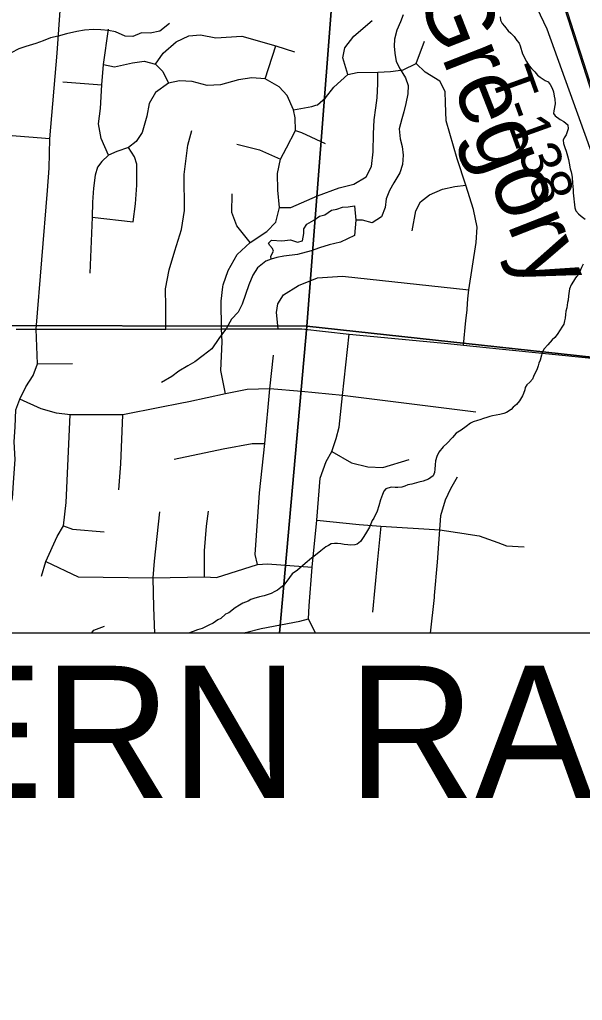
# Model space of a CAD drawing. Extents: x 0 to 34, y 0 to 22.
# Drawn here: x 7.388 to 8.182, y 18.207 to 19.591 of the extents above; entities that cross this region are included whole.
import ezdxf

# ---------------------------------------------------------------- set-up
doc = ezdxf.new("R2010")
doc.units = 0
for name, color, linetype in [('GM_X_County_Road', 7, 'Continuous'), ('GM_X_Minor_River', 7, 'Continuous'), ('GM_X_Minor_River_Text', 7, 'Continuous'), ('GM_X_Rail_Line', 7, 'Continuous'), ('GM_X_Section', 7, 'Continuous'), ('GM_X_Township_Road', 7, 'Continuous'), ('GM_X_Township_Road_Text', 7, 'Continuous'), ('SH_Text', 7, 'Continuous')]:
    doc.layers.add(name, color=color, linetype=linetype)

msp = doc.modelspace()

# ---------------------------------------------------------------- linework, layer by layer
at = {"layer": 'GM_X_County_Road'}
for points in [[(7.3836, 19.1544), (7.4116, 19.1543), (7.5209, 19.1543), (7.5946, 19.1542), (7.6731, 19.1546), (7.7531, 19.1546), (7.7867, 19.1546), (7.8535, 19.1472), (7.9926, 19.134)], [(7.9926, 19.134), (8.0146, 19.1319), (8.0648, 19.1263), (8.261, 19.1068)]]:
    msp.add_lwpolyline(points, dxfattribs=at)
at = {"layer": 'GM_X_Minor_River'}
for points in [[(7.9296, 19.5977), (7.9259, 19.5879), (7.9207, 19.5763), (7.9173, 19.5634), (7.9167, 19.5536), (7.9176, 19.5437), (7.9195, 19.5318), (7.9253, 19.521), (7.933, 19.5087), (7.9365, 19.4983), (7.9362, 19.4862), (7.9332, 19.4726), (7.9303, 19.4608), (7.9278, 19.451), (7.924, 19.4371), (7.9255, 19.4229), (7.9283, 19.4122), (7.9295, 19.3997), (7.9288, 19.3864), (7.9247, 19.3747), (7.9164, 19.3608), (7.9104, 19.35), (7.9056, 19.3383), (7.9041, 19.3258), (7.8988, 19.3126), (7.8857, 19.3042), (7.8721, 19.308)], [(7.5999, 19.5856), (7.586, 19.5749), (7.5726, 19.5718), (7.5605, 19.5722), (7.5482, 19.5671), (7.5372, 19.5678), (7.5237, 19.5739), (7.5138, 19.5756), (7.5032, 19.5767), (7.4926, 19.5773), (7.48, 19.5761), (7.469, 19.5741), (7.4545, 19.5711), (7.4426, 19.5679), (7.4319, 19.5652), (7.4215, 19.5609), (7.4112, 19.5573), (7.3974, 19.5531), (7.3874, 19.5496), (7.3767, 19.5441), (7.3624, 19.5346), (7.3493, 19.5274)], [(8.0662, 19.5951), (8.0668, 19.5901), (8.0693, 19.5858), (8.0723, 19.5819), (8.0778, 19.5753), (8.0815, 19.5718), (8.0859, 19.5671), (8.0899, 19.5616), (8.0932, 19.5577), (8.0946, 19.5543), (8.0977, 19.5428), (8.1035, 19.532), (8.1075, 19.5258), (8.1104, 19.5222), (8.1152, 19.5172), (8.1192, 19.5125), (8.123, 19.5097), (8.13, 19.5053), (8.1342, 19.5033), (8.1367, 19.4994), (8.1396, 19.4944), (8.1414, 19.489), (8.1427, 19.4829), (8.1433, 19.4787), (8.1439, 19.4722), (8.1421, 19.4624), (8.1416, 19.4586), (8.1438, 19.4551), (8.1509, 19.4503), (8.1561, 19.4475), (8.1617, 19.4428), (8.1622, 19.437), (8.161, 19.4325), (8.1593, 19.4284), (8.1565, 19.4243), (8.1553, 19.4209), (8.1559, 19.4163), (8.1577, 19.4106), (8.1594, 19.4052), (8.1615, 19.3987), (8.1629, 19.3937), (8.1635, 19.3887), (8.1651, 19.3807), (8.1665, 19.3761), (8.1675, 19.3715), (8.1678, 19.3681), (8.1684, 19.3604), (8.1692, 19.3509), (8.1695, 19.3464), (8.1697, 19.3429), (8.1703, 19.3376), (8.1706, 19.3338), (8.1715, 19.3254), (8.1729, 19.3212), (8.1769, 19.3169), (8.1807, 19.3137)], [(7.8115, 19.3137), (7.8188, 19.3158), (7.8284, 19.322), (7.8361, 19.3237), (7.8441, 19.3262), (7.8521, 19.3271), (7.8609, 19.3284), (7.8626, 19.3082)], [(7.8626, 19.3082), (7.8609, 19.2862), (7.8413, 19.2772), (7.8249, 19.2731), (7.8115, 19.2692), (7.7996, 19.2646), (7.7805, 19.2594), (7.7611, 19.2572), (7.7511, 19.2556), (7.7431, 19.2531), (7.7428, 19.2573), (7.7464, 19.2641), (7.745, 19.2683), (7.7413, 19.2725), (7.7395, 19.2756), (7.7438, 19.2797), (7.7582, 19.279), (7.7708, 19.2802), (7.7806, 19.2769), (7.7874, 19.279), (7.7892, 19.2892), (7.7894, 19.296), (7.7937, 19.3024), (7.8034, 19.3082), (7.8115, 19.3137)], [(7.8721, 19.308), (7.8626, 19.3082)], [(8.1807, 19.3137), (8.1862, 19.3097)], [(7.7431, 19.2531), (7.7358, 19.2503), (7.7242, 19.2407), (7.7175, 19.2306), (7.7118, 19.217), (7.7069, 19.2031), (7.7024, 19.1895), (7.6968, 19.1783), (7.6874, 19.1682), (7.6803, 19.1555), (7.6696, 19.1413), (7.6598, 19.1264), (7.6474, 19.1172), (7.6354, 19.108), (7.6257, 19.1025), (7.613, 19.0949), (7.603, 19.0875), (7.5887, 19.0788)], [(8.1836, 19.2459), (8.1812, 19.2411), (8.1783, 19.2347), (8.1763, 19.2313), (8.1728, 19.2265), (8.1696, 19.222), (8.1664, 19.2168), (8.164, 19.2112), (8.1634, 19.2048), (8.1629, 19.2013), (8.1623, 19.1953), (8.1615, 19.1919), (8.1605, 19.1843), (8.1592, 19.1798), (8.1587, 19.1749), (8.1582, 19.1696), (8.1573, 19.1658), (8.156, 19.1613), (8.1532, 19.1572), (8.1508, 19.1534), (8.1468, 19.1467), (8.1437, 19.1423), (8.1398, 19.139), (8.1335, 19.1323), (8.1284, 19.1264), (8.1256, 19.1215), (8.1247, 19.1178), (8.123, 19.1106), (8.1209, 19.1061), (8.1201, 19.1027), (8.118, 19.097), (8.1164, 19.0937), (8.1136, 19.0873), (8.1119, 19.0839), (8.1084, 19.0795), (8.1041, 19.0758), (8.1017, 19.0721), (8.1012, 19.0687), (8.0992, 19.0634), (8.0979, 19.06), (8.0935, 19.0533), (8.0896, 19.0481), (8.0849, 19.0441), (8.0818, 19.0408), (8.0752, 19.0368), (8.0714, 19.0354), (8.066, 19.034), (8.0606, 19.033), (8.0557, 19.0321), (8.0518, 19.031), (8.0476, 19.0296), (8.043, 19.0283), (8.0376, 19.0261), (8.0342, 19.0255), (8.0284, 19.0234), (8.0246, 19.0216), (8.0184, 19.0169), (8.0114, 19.0117), (8.0044, 19.0074), (7.9989, 19.0015), (7.9914, 18.9933), (7.986, 18.9882), (7.98, 18.9808), (7.9768, 18.9748), (7.9751, 18.9684), (7.9746, 18.9627), (7.974, 18.9566), (7.9735, 18.9521), (7.9718, 18.9472), (7.9652, 18.9428), (7.9579, 18.94), (7.9514, 18.9383), (7.9418, 18.9356), (7.9361, 18.9346), (7.9319, 18.9328), (7.9277, 18.9314), (7.9219, 18.9309), (7.9181, 18.931), (7.9128, 18.9311), (7.9052, 18.9291), (7.9024, 18.9257), (7.9004, 18.9212), (7.8975, 18.9134), (7.8953, 18.9051), (7.8928, 18.8975), (7.888, 18.8878), (7.886, 18.8844)], [(7.886, 18.8844), (7.8819, 18.8747), (7.8763, 18.8653), (7.8731, 18.8601), (7.8695, 18.8545), (7.8648, 18.8509), (7.8614, 18.8498), (7.8553, 18.8496), (7.8515, 18.8501), (7.8462, 18.8503), (7.8417, 18.8512), (7.8367, 18.8517), (7.8326, 18.8519), (7.828, 18.8512), (7.8241, 18.8491), (7.8203, 18.8473), (7.8133, 18.8414), (7.8059, 18.8352), (7.8004, 18.8312), (7.7911, 18.8235), (7.7875, 18.8202), (7.7805, 18.8143), (7.7728, 18.8092), (7.7692, 18.804), (7.7668, 18.8007), (7.7605, 18.7925), (7.757, 18.7899), (7.752, 18.7859), (7.7485, 18.7841), (7.7435, 18.7812), (7.7335, 18.7781), (7.727, 18.7768), (7.7189, 18.774), (7.7147, 18.773), (7.7108, 18.7704), (7.7031, 18.7676), (7.6985, 18.7647), (7.6927, 18.7611), (7.6837, 18.7538), (7.6791, 18.752), (7.6725, 18.7461), (7.6679, 18.744), (7.6613, 18.7396), (7.6555, 18.7368), (7.6458, 18.7321), (7.6393, 18.73), (7.6332, 18.7276), (7.6267, 18.7255)]]:
    msp.add_lwpolyline(points, dxfattribs=at)
at = {"layer": 'GM_X_Rail_Line'}
for points in [[(8.4398, 18.7255), (8.417, 18.7971), (8.3229, 19.0903), (8.2261, 19.3934), (8.0982, 19.7915), (8.0194, 20.0387), (7.8397, 20.5967), (7.7636, 20.8402), (7.7444, 20.9)], [(8.4419, 18.7255), (8.4189, 18.7977), (8.3247, 19.0909), (8.2279, 19.394), (8.1001, 19.7921), (8.0212, 20.0393), (7.8415, 20.5972), (7.7654, 20.8408), (7.7464, 20.9)]]:
    msp.add_lwpolyline(points, dxfattribs=at)
at = {"layer": 'GM_X_Section'}
for points in [[(6.8362, 20.1611), (6.8487, 20.1601), (7.855, 20.0664), (7.8637, 20.0659), (7.7938, 19.1583), (6.7522, 19.1603)], [(7.8637, 20.0659), (8.8506, 19.9738), (8.8752, 19.9725), (8.7834, 19.051), (7.7938, 19.1583)]]:
    msp.add_lwpolyline(points, close=True, dxfattribs=at)
for points in [[(6.7169, 18.7255), (6.7522, 19.1603), (7.7938, 19.1583), (7.7552, 18.7255)], [(7.7552, 18.7255), (7.7938, 19.1583), (8.7834, 19.051), (8.7546, 18.7255)]]:
    msp.add_lwpolyline(points, dxfattribs=at)
at = {"layer": 'GM_X_Township_Road'}
for p, q in [((7.7347, 19.5073), (7.7501, 19.554)), ((7.4492, 19.5031), (7.5044, 19.4991)), ((7.7412, 19.0701), (7.7468, 19.1178)), ((7.4135, 19.1053), (7.4631, 19.106)), ((7.898, 18.8761), (7.8933, 18.8291)), ((7.7072, 18.7255), (7.707, 18.7261))]:
    msp.add_line(p, q, dxfattribs=at)
for points in [[(8.2019, 19.3849), (8.1906, 19.4173), (8.1328, 19.5778), (8.1185, 19.6074), (8.1051, 19.6338), (8.0979, 19.6497), (8.0885, 19.673), (8.0618, 19.7259), (8.0472, 19.7513), (8.0345, 19.7741), (8.0218, 19.7987), (8.0153, 19.8143), (8.0057, 19.8401), (7.996, 19.8652), (7.9885, 19.8873), (7.9832, 19.9061), (7.9805, 19.9239), (7.9729, 19.994), (7.9667, 20.0283), (7.9624, 20.049)], [(7.4116, 19.1543), (7.4279, 19.3499), (7.4299, 19.3814), (7.431, 19.423), (7.4413, 19.5439), (7.449, 19.6509), (7.4607, 19.7828), (7.4673, 19.8582), (7.469, 19.9012)], [(7.8513, 19.5136), (7.8442, 19.5372), (7.8471, 19.5514), (7.86, 19.5677), (7.886, 19.59)], [(7.5138, 19.3998), (7.5033, 19.4235), (7.4999, 19.444), (7.5025, 19.4658), (7.5044, 19.4991), (7.5067, 19.5275), (7.5136, 19.5774)], [(7.5803, 19.528), (7.5908, 19.5438), (7.6094, 19.5595), (7.6273, 19.5682), (7.6438, 19.5698), (7.6654, 19.5653), (7.7019, 19.5679), (7.7501, 19.554), (7.776, 19.5454)], [(7.8065, 19.4703), (7.8088, 19.471), (7.8198, 19.4805), (7.8316, 19.4957), (7.8513, 19.5136), (7.8645, 19.5165), (7.8939, 19.517), (7.9115, 19.518), (7.9293, 19.5201), (7.9477, 19.5293), (7.9595, 19.5608)], [(7.5067, 19.5275), (7.5225, 19.5246), (7.5475, 19.5301), (7.5643, 19.5325), (7.5803, 19.528), (7.5903, 19.518), (7.5984, 19.5015)], [(8.02, 19.1823), (8.0207, 19.1971), (8.0223, 19.2099), (8.0323, 19.2767), (8.0339, 19.2982), (8.0286, 19.3232), (8.0181, 19.3576), (8.0058, 19.3946), (7.99, 19.4484), (7.9892, 19.4734), (7.9887, 19.4897), (7.9811, 19.5044), (7.9606, 19.517), (7.9477, 19.5293)], [(7.7549, 19.326), (7.7712, 19.326), (7.8085, 19.3426), (7.839, 19.3536), (7.8597, 19.3591), (7.8771, 19.3691), (7.885, 19.3836), (7.8873, 19.4046), (7.8878, 19.43), (7.8886, 19.4497), (7.891, 19.4668), (7.8928, 19.4807), (7.8939, 19.5004), (7.8939, 19.517)], [(7.6751, 19.2139), (7.6754, 19.2167), (7.6825, 19.2372), (7.6952, 19.2595), (7.7136, 19.2766), (7.7372, 19.2923), (7.7497, 19.3053), (7.7549, 19.326), (7.7526, 19.3505), (7.7523, 19.3738), (7.7563, 19.3943), (7.7647, 19.4101), (7.7775, 19.4345), (7.777, 19.4524), (7.7746, 19.4637), (7.766, 19.4839), (7.7544, 19.496), (7.7347, 19.5073), (7.7158, 19.5091), (7.6974, 19.5062), (7.672, 19.4991), (7.6528, 19.4983), (7.632, 19.5036), (7.6139, 19.5046), (7.5984, 19.5015), (7.58, 19.4881), (7.5714, 19.4729), (7.5679, 19.4547), (7.5614, 19.4316), (7.553, 19.419), (7.5419, 19.4106), (7.5257, 19.4048), (7.5138, 19.3998), (7.5046, 19.3909), (7.4983, 19.3828), (7.4952, 19.3717), (7.4928, 19.3531), (7.4912, 19.3334), (7.4908, 19.3122), (7.4873, 19.2333)], [(7.7746, 19.4637), (7.8009, 19.4684), (7.8065, 19.4703)], [(7.431, 19.423), (7.3716, 19.4275), (7.3532, 19.4287), (7.3204, 19.4322)], [(7.5946, 19.1542), (7.5948, 19.1858), (7.5942, 19.2111), (7.5992, 19.2378), (7.6073, 19.2648), (7.617, 19.2949), (7.6209, 19.3219), (7.6207, 19.3725), (7.6257, 19.4137), (7.6312, 19.4348)], [(7.7775, 19.4345), (7.7863, 19.4319), (7.8193, 19.4164)], [(7.4908, 19.3122), (7.5488, 19.3058), (7.5517, 19.3313), (7.5538, 19.3573), (7.554, 19.3749), (7.5538, 19.3872), (7.5506, 19.3975), (7.5419, 19.4106)], [(7.695, 19.4154), (7.7269, 19.4072), (7.7563, 19.3943)], [(7.9422, 19.2929), (7.9475, 19.3213), (7.954, 19.3339), (7.9669, 19.3439), (7.985, 19.3518), (8.0024, 19.3557), (8.0181, 19.3576)], [(7.7136, 19.2766), (7.6947, 19.2999), (7.688, 19.3191), (7.6881, 19.3452)], [(7.7531, 19.1546), (7.751, 19.1776), (7.7527, 19.1901), (7.7606, 19.2029), (7.7819, 19.2161), (7.8085, 19.2269), (7.844, 19.2289), (8.0223, 19.2099)], [(7.6731, 19.1546), (7.6728, 19.1937), (7.6751, 19.2139)], [(8.0146, 19.1319), (8.0179, 19.1663), (8.02, 19.1813), (8.02, 19.1823)], [(7.3309, 18.7255), (7.331, 18.7269), (7.3326, 18.7677), (7.3356, 18.7999), (7.3422, 18.8262), (7.3691, 18.882), (7.3734, 18.8952), (7.3786, 18.9156), (7.3803, 18.9445), (7.3823, 18.9705), (7.3806, 18.9952), (7.3823, 19.0165), (7.3829, 19.0405), (7.3888, 19.0557), (7.3974, 19.0728), (7.4076, 19.0889), (7.4135, 19.1053), (7.4116, 19.1543)], [(7.6791, 19.0632), (7.6721, 19.0959), (7.674, 19.1363), (7.6731, 19.1546)], [(7.8058, 18.7255), (7.7961, 18.7453), (7.797, 18.7637), (7.801, 18.8183), (7.8079, 18.8847), (7.8122, 18.9439), (7.8207, 18.9677), (7.829, 18.9817), (7.8352, 18.9999), (7.8394, 19.0162), (7.8437, 19.0606), (7.8535, 19.1472)], [(8.0322, 19.0372), (7.8437, 19.0606), (7.7862, 19.0662), (7.7412, 19.0701), (7.7096, 19.0691), (7.6791, 19.0632), (7.6271, 19.0517), (7.6149, 19.0493)], [(7.7241, 18.8222), (7.7205, 18.8364), (7.727, 18.9235), (7.7343, 18.9929), (7.7412, 19.0701)], [(7.6149, 19.0493), (7.5864, 19.0438), (7.5341, 19.0333), (7.4598, 19.0333), (7.4404, 19.0356), (7.4188, 19.0418), (7.3888, 19.0557)], [(7.4191, 18.8055), (7.4254, 18.8265), (7.4415, 18.8619), (7.4501, 18.8768), (7.4539, 18.9097), (7.4598, 19.0333)], [(7.5285, 18.9276), (7.5311, 18.9641), (7.5341, 19.0333)], [(7.6064, 18.9709), (7.6756, 18.9856), (7.7164, 18.9931), (7.7343, 18.9929)], [(7.829, 18.9817), (7.8565, 18.9656), (7.8795, 18.9601), (7.9009, 18.9591), (7.9378, 18.9703)], [(7.9813, 18.8709), (7.9827, 18.8913), (7.9893, 18.9133), (7.9966, 18.9294), (8.0061, 18.9458)], [(7.5791, 18.7255), (7.5776, 18.7617), (7.577, 18.8036), (7.5785, 18.8267), (7.586, 18.8965)], [(7.6491, 18.8048), (7.6494, 18.8414), (7.6521, 18.8763), (7.6549, 18.8975)], [(7.4501, 18.8768), (7.4629, 18.8722), (7.5078, 18.8682)], [(7.8079, 18.8847), (7.8675, 18.8785), (7.898, 18.8761), (7.9813, 18.8709), (8.0156, 18.866), (8.0214, 18.865)], [(7.9738, 18.7786), (7.9781, 18.8255), (7.9813, 18.8709)], [(8.0214, 18.865), (8.0369, 18.8626), (8.0629, 18.8531), (8.0751, 18.8485), (8.1001, 18.8469)], [(7.4254, 18.8265), (7.471, 18.8048), (7.577, 18.8036), (7.6491, 18.8048), (7.6662, 18.8038), (7.7241, 18.8222), (7.7379, 18.8232), (7.801, 18.8183)], [(7.8933, 18.8291), (7.8928, 18.8244), (7.8864, 18.7547)], [(7.9683, 18.7255), (7.9735, 18.7756), (7.9738, 18.7786)], [(7.7054, 18.7255), (7.707, 18.7261), (7.729, 18.7317), (7.7839, 18.7423), (7.7961, 18.7453)], [(7.4897, 18.7255), (7.4931, 18.7296), (7.5082, 18.735)]]:
    msp.add_lwpolyline(points, dxfattribs=at)
at = {"layer": 'SH_Text'}
msp.add_lwpolyline([(8.8041, 18.7255), (5.1102, 18.7255), (5.1102, 18.1592), (8.8041, 18.1592)], close=True, dxfattribs=at)

# ---------------------------------------------------------------- texts
at = {"layer": 'GM_X_Minor_River_Text'}
msp.add_text('Gregory', height=0.09469, rotation=291.3879, dxfattribs=at).set_placement((7.9475, 19.6299))
at = {"layer": 'GM_X_Township_Road_Text'}
msp.add_text('T-138', height=0.05682, rotation=289.768, dxfattribs=at).set_placement((8.0521, 19.5124))
at = {"layer": 'SH_Text'}
msp.add_text('NORFOLK SOUTHERN RAILWAY', height=0.18634, dxfattribs=at).set_placement((5.1099, 18.4929))

doc.saveas('drawing.dxf')
